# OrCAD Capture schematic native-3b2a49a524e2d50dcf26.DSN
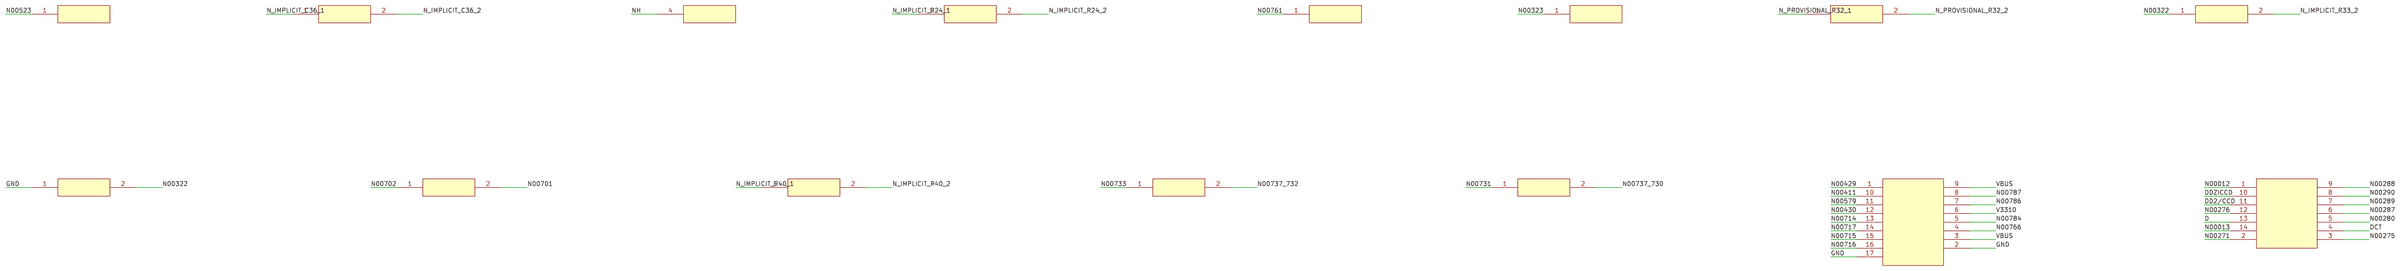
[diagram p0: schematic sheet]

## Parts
C32  100K
C36  100K
R6  100K
R8  10K
R16  100K
R24  10K
R26  22K
R31  10K
R32  100K
R33  100K
R34  22K
R38  10K
R40  100K
U2  UNKNOWN
U58  UNKNOWN

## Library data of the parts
C32 = OBS_C32
C36 = OBS_C36
R6 = OBS_R6
R8 = OBS_R8
R16 = OBS_R16
R24 = OBS_R24
R26 = OBS_R26
R31 = OBS_R31
R32 = OBS_R32
R33 = OBS_R33
R34 = OBS_R34
R38 = OBS_R38
R40 = OBS_R40
U2 = OBS_U2
U58 = OBS_U58

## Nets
GND: R34.1 U2.2 U2.17
V3310: U2.6
VBUS: U2.3 U2.9
D: U58.13
DCT: U58.4
DD2/CCD: U58.11
DDZICCD: U58.10
N00737_730: R8.2
N00737_732: R6.2
N_IMPLICIT_C36_1: C36.1
N_IMPLICIT_C36_2: C36.2
N_IMPLICIT_R24_1: R24.1
N_IMPLICIT_R24_2: R24.2
N_IMPLICIT_R33_2: R33.2
N_IMPLICIT_R40_1: R40.1
N_IMPLICIT_R40_2: R40.2
N_PROVISIONAL_R32_1: R32.1
N_PROVISIONAL_R32_2: R32.2
NH: R16.4
N00322: R33.1 R34.2

Not connected (* = marked no-connect by the designer): C32 1; R6 1; R8 1; R26 1; R31 1; R38 1 2; U2 1 4 5 7 8 10 11 12 13 14 15 16; U58 1 2 3 5 6 7 8 9 12 14
